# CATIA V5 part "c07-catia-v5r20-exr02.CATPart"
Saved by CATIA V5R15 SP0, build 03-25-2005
Part number: Part1
Bounding box of the stored display mesh (mm): x -23 to 23, y -104 to 104, z 0 to 68
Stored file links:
  D:\v5_r20\psrt_files_downloaded\c07-catia-v5r20-prt\c07-catia-v5r20-exr02.CATPart
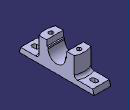
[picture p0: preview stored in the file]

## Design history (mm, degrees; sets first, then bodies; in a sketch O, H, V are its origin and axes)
Body1 (main body)
  Sketch1 on yz-plane, origin (0, 0, 0), H (0, 1, 0), V (0, 0, 1)
    point P1 (-104, 0)
    line L1 (-104, 0) -> (-100, 14)
    point P2 (-100, 14)
    line L2 (-100, 14) -> (-54, 14)
    point P3 (-54, 14)
    line L3 (-54, 14) -> (-54, 68)
    point P4 (-54, 68)
    line L4 (-54, 68) -> (-28, 68)
    point P5 (-28, 68)
    line L5 (-28, 68) -> (-28, 52)
    point P6 (-28, 52)
    line L6 (-28, 52) -> (-24, 52)
    point P7 (-24, 52)
    line L7 (-24, 52) -> (-24, 48)
    point P8 (-24, 48)
    point P9 (100, 14)
    point P10 (104, 0)
    line L8 (104, 0) -> (100, 14)
    point P11 (54, 14)
    line L9 (100, 14) -> (54, 14)
    point P12 (54, 68)
    line L10 (54, 14) -> (54, 68)
    point P13 (28, 68)
    line L11 (54, 68) -> (28, 68)
    point P14 (28, 52)
    line L12 (28, 68) -> (28, 52)
    point P15 (24, 52)
    line L13 (28, 52) -> (24, 52)
    point P16 (24, 48)
    line L14 (24, 52) -> (24, 48)
    line L15 (-104, 0) -> (104, 0)
    arc A1 centre (0, 48) radius 24 from (-24, 48) to (24, 48) ccw
    point P18 (0, 24)
    length L15 = 208
    distance L3 L10 = 108
    distance L15 L2 = 14
    length L1 H = 4
    length L5 = 16
    distance L5 L12 = 56
    radius A1 = 24
    distance P7 P8 = 4
    distance L15 L4 = 68
    coincidence: P1 H, A1 P18
    horizontal: L2 H, L4 H, L6 H, L15 H
    vertical: L3 V, L5 V, L7 V
    symmetry: P2 P9 V, P1 P10 V, L1 L8 V, P3 P11 V, L2 L9 V, P4 P12 V, L3 L10 V, P5 P13 V, L4 L11 V, P6 P14 V, L5 L12 V, P7 P15 V, L6 L13 V, P8 P16 V, L7 L14 V
    tangency: L7 A1, A1 L14
  Pad1: profile Sketch1, direction (1, 0, 0), length 23, mirrored extent
  Sketch2 on face of Pad1 from Sketch1.L11, origin (0, 0, 68), H (1, 0, 0), V (0, 1, 0)
    circle A1 centre (0, 0) radius 54
    point P1 (0, 54)
    reference projected line E1 (-23, 54) -> (23, 54) from edge [face of Pad1 from Sketch1.L11 | face of Pad1 from Sketch1.L10]
    coincidence: A1 P1, P1 V
    tangency: A1 E1
  Pocket1: profile Sketch2, direction (0, 0, -1), length 54, outer side
  Fillet1: radius 8, on edge [face of Pocket1 | face of Pocket1] (x2)
  Sketch3 on face of Pad1 from Sketch1.L15, origin (0, 0, 0), H (1, 0, 0), V (0, -1, 0)
    point P1 (-13.1636, -26)
    line L1 (-13.1636, -26) -> (12.8364, -26)
    line L2 (12.8364, -26) -> (12.8364, -52)
    line L3 (12.8364, -52) -> (-13.1636, -52)
    line L4 (-13.1636, -52) -> (-13.1636, -26)
    point P2 (12.8364, -26)
    point P3 (12.8364, -52)
    point P4 (-13.1636, -52)
    reference projected line E1 (-23, 104) -> (-23, -104) from edge [start face of Pad1 | face of Pad1 from Sketch1.L15]
    point P5 (-13.1636, 26)
    point P6 (12.8364, 26)
    point P7 (12.8364, 52)
    point P8 (-13.1636, 52)
    line L5 (-13.1636, 26) -> (12.8364, 26)
    line L6 (12.8364, 26) -> (12.8364, 52)
    line L7 (12.8364, 52) -> (-13.1636, 52)
    line L8 (-13.1636, 52) -> (-13.1636, 26)
    length L2 = 26
    length L3 = 26
    distance L1 H = 26
    distance L4 E1 = 9.8364
    horizontal: L1 H, L3 H
    vertical: L2 V, L4 V
    symmetry: P1 P5 H, P2 P6 H, P3 P7 H, P4 P8 H, L1 L5 H, L2 L6 H, L3 L7 H, L4 L8 H
  Pocket2: profile Sketch3, direction (0, 0, 1), length 10
  Sketch4 on end face of Pocket2, origin (-3.5145, -39.4683, 10), H (1, 0, 0), V (0, -1, 0)
    point P1 (3.3508, -0.4683)
    reference projected line E1 (16.3508, 12.5317) -> (-9.6492, 12.5317) from edge [face of Pad1 from Sketch1.L15 | face of Pocket2 from Sketch3.L7]
    reference projected line E2 (-9.6492, 12.5317) -> (-9.6492, -13.4683) from edge [face of Pad1 from Sketch1.L15 | face of Pocket2 from Sketch3.L8]
    reference intersected line E3 through (0, -39.4683) direction (1, 0) from zx-plane
    point P4 (3.3508, -78.4683)
    distance E1 P1 = 13
    distance P1 E2 = 13
    symmetry: P1 P4 E3
  Hole1: placed by Sketch4, at (-0.1636, -39, 10) direction (0, 0, 1), diameter 12, through (limit type 3)
  Sketch5 on end face of Pocket2, origin (1.3648, 40.5284, 10), H (1, 0, 0), V (0, -1, 0)
    point P1 (-1.5284, 1.5284)
    reference projected line E1 (11.4716, 14.5284) -> (-14.5284, 14.5284) from edge [face of Pad1 from Sketch1.L15 | face of Pocket2 from Sketch3.L1]
    reference projected line E2 (11.4716, -11.4716) -> (11.4716, 14.5284) from edge [face of Pad1 from Sketch1.L15 | face of Pocket2 from Sketch3.L2]
    distance P1 E1 = 13
    distance E2 P1 = 13
  Hole2: placed by Sketch5, at (-0.1636, 39, 10) direction (0, 0, 1), diameter 12, through (limit type 3)
  Sketch6 on face of Pocket1, origin (0, 0, 14), H (1, 0, 0), V (0, 1, 0)
    construction line L1 (0, -85) -> (0, -77)
    point P1 (0, -85)
    point P2 (0, -77)
    line L2 (-6, -85) -> (-6, -77)
    line L3 (6, -77) -> (6, -85)
    arc A1 centre (0, -77) radius 6 from (-6, -77) to (6, -77) cw
    arc A2 centre (0, -85) radius 6 from (6, -85) to (-6, -85) cw
    point P3 (-6, -85)
    point P4 (-6, -77)
    point P5 (6, -77)
    point P6 (6, -85)
    construction line L4 (0, 85) -> (0, 77)
    point P9 (-6, 85)
    point P10 (-6, 77)
    point P11 (6, 77)
    point P12 (6, 85)
    line L5 (-6, 85) -> (-6, 77)
    line L6 (6, 77) -> (6, 85)
    arc A3 centre (0, 77) radius 6 from (-6, 77) to (6, 77) ccw
    arc A4 centre (0, 85) radius 6 from (6, 85) to (-6, 85) ccw
    distance L1 L2 = 6
    distance A2 A1 = 20
    distance P2 H = 77
    coincidence: P1 V
    vertical: L1 V
    tangency: A1 L2, A2 L2, A1 L3, A2 L3
    symmetry: L1 L4 H, P3 P9 H, P4 P10 H, P5 P11 H, P6 P12 H, L2 L5 H, L3 L6 H, A1 A3 H, A2 A4 H
  Pocket3: profile Sketch6, direction (0, 0, -1), through (limit type 3)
